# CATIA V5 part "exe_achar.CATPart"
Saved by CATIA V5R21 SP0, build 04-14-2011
Part number: exe_achar
Bounding box of the stored display mesh (mm): x -70.161 to 69.255, y -15.991 to 15.975, z -2.5 to 2.5
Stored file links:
  C:\Users\amir\Desktop\exe_achar.CATPart
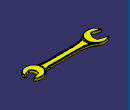
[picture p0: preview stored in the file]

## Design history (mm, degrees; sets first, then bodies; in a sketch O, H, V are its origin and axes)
Body1 (main body)
  Sketch1 on xy-plane, origin (0, 0, 0), H (1, 0, 0), V (0, 1, 0)
    construction line L1 (-55, 0) -> (55, 0)
    point P1 (-55, 0)
    point P2 (55, 0)
    arc A1 centre (55, 0) radius 14.5 from (65.3713, 10.1334) to (69.324, -2.2521) ccw
    arc A2 centre (61, 2) radius 9 from (53.1466, 6.396) to (56.9475, -6.036) ccw
    point P3 (61, 2)
    construction line L2 (89.6784, 10.7679) -> (34.5526, -6.0858)
    line L3 (56.9475, -6.036) -> (69.324, -2.2521)
    line L4 (53.1466, 6.396) -> (65.3713, 10.1334)
    arc A3 centre (-55, 0) radius 16 from (-70.3082, -4.6541) to (-65.8495, 11.7596) ccw
    point P10 (-55, 0)
    arc A4 centre (-63, 2) radius 13 from (-56.0788, -9.0044) to (-51.1085, 7.2528) ccw
    point P11 (-63, 2)
    axis line L5 (-86.4605, 9.1726) -> (-22.1521, -10.4884)
    line L6 (-70.3082, -4.6541) -> (-56.0788, -9.0044)
    line L7 (-65.8495, 11.7596) -> (-51.1085, 7.2528)
    length L1 = 110
    radius A1 = 14.5
    radius A2 = 9
    distance P3 P2 H = 6
    distance P3 P2 V = 2
    angle L2 L1 = 17
    distance L2 L3 = 6.5
    radius A3 = 16
    radius A4 = 13
    distance P11 P10 H = 8
    distance P11 P1 V = 2
    angle L5 L1 = 17
    distance L5 L6 = 8.5
    coincidence: P1 H, L2 P3, P10 P1, L5 P11
    horizontal: L1 H
    symmetry: P2 P1 V, L3 L4 L2, L6 L7 L5
  Pad1: profile Sketch1, direction (0, 0, 1), length 2.5, mirrored extent
  Sketch2 on xy-plane, origin (0, 0, 0), H (1, 0, 0), V (0, 1, 0)
    line L1 (-40.1676, 6) -> (41.7996, 6)
    line L2 (-40.1676, -6) -> (41.7996, -6)
    projected arc E1 centre (55, 0) radius 14.5 from (65.3713, 10.1334) to (69.324, -2.2521) ccw from edge [face of Pad1 from Sketch1.A1 | end face of Pad1]
    projected arc E2 centre (55, 0) radius 14.5 from (41.7996, 6) to (41.7996, -6) ccw from edge [face of Pad1 from Sketch1.A1 | end face of Pad1]
    projected arc E3 centre (-55, 0) radius 16 from (-70.3082, -4.6541) to (-65.8495, 11.7596) ccw from edge [face of Pad1 from Sketch1.A3 | end face of Pad1]
    projected arc E4 centre (-55, 0) radius 16 from (-40.1676, -6) to (-40.1676, 6) ccw from edge [face of Pad1 from Sketch1.A3 | end face of Pad1]
    point P5 (41.7996, 6)
    point P6 (41.7996, -6)
    point P8 (-40.1676, 6)
    point P9 (-40.1676, 6)
    point P10 (41.7996, -6)
    point P11 (41.7996, 6)
    distance L1 L2 = 12
    horizontal: L1 H
    symmetry: L1 L2 H
    coincidence: L1 P5, L2 P6, L1 P8, E3 P9, E1 P10, E1 P11, P5 P11, P6 P10, P8 P9
  Pad2: profile Sketch2, direction (0, 0, 1), length 2, mirrored extent
  Fillet1: radius 47, on edge [face of Pad1 from Sketch1.A3 | face of Pad2 from Sketch2.L1]
  Fillet2: radius 47, on edge [face of Pad2 from Sketch2.L2 | face of Pad1 from Sketch1.A3]
  Fillet3: radius 23, on edge [face of Pad1 from Sketch1.A1 | face of Pad2 from Sketch2.L2]
  Fillet4: radius 23, on edge [face of Pad2 from Sketch2.L1 | face of Pad1 from Sketch1.A1]
  Sketch3 on end face of Pad2, origin (0, 0, 2), H (1, 0, 0), V (0, 1, 0)
  Pocket1: profile Sketch3, direction (0, 0, -1), length 0.5
  Mirror1: of Pocket1, about xy-plane
  Fillet5: radius 0.5, on start face of Pad1 (x2); start face of Pad2; face of Mirror1; end face of Pad1 (x2); end face of Pad2; end face of Pocket1
  Fillet6: radius 0.25, on edge [face of Pad1 from Sketch1.L3 | face of Pad1 from Sketch1.A1]; edge [face of Pad1 from Sketch1.A1 | face of Pad1 from Sketch1.L4]; edge [face of Pad1 from Sketch1.A3 | face of Pad1 from Sketch1.L6]; edge [face of Pad1 from Sketch1.L7 | face of Pad1 from Sketch1.A3]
